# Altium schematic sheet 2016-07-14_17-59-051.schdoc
size 339 x 185 mm; SheetNumber: 1; SheetTotal: 1
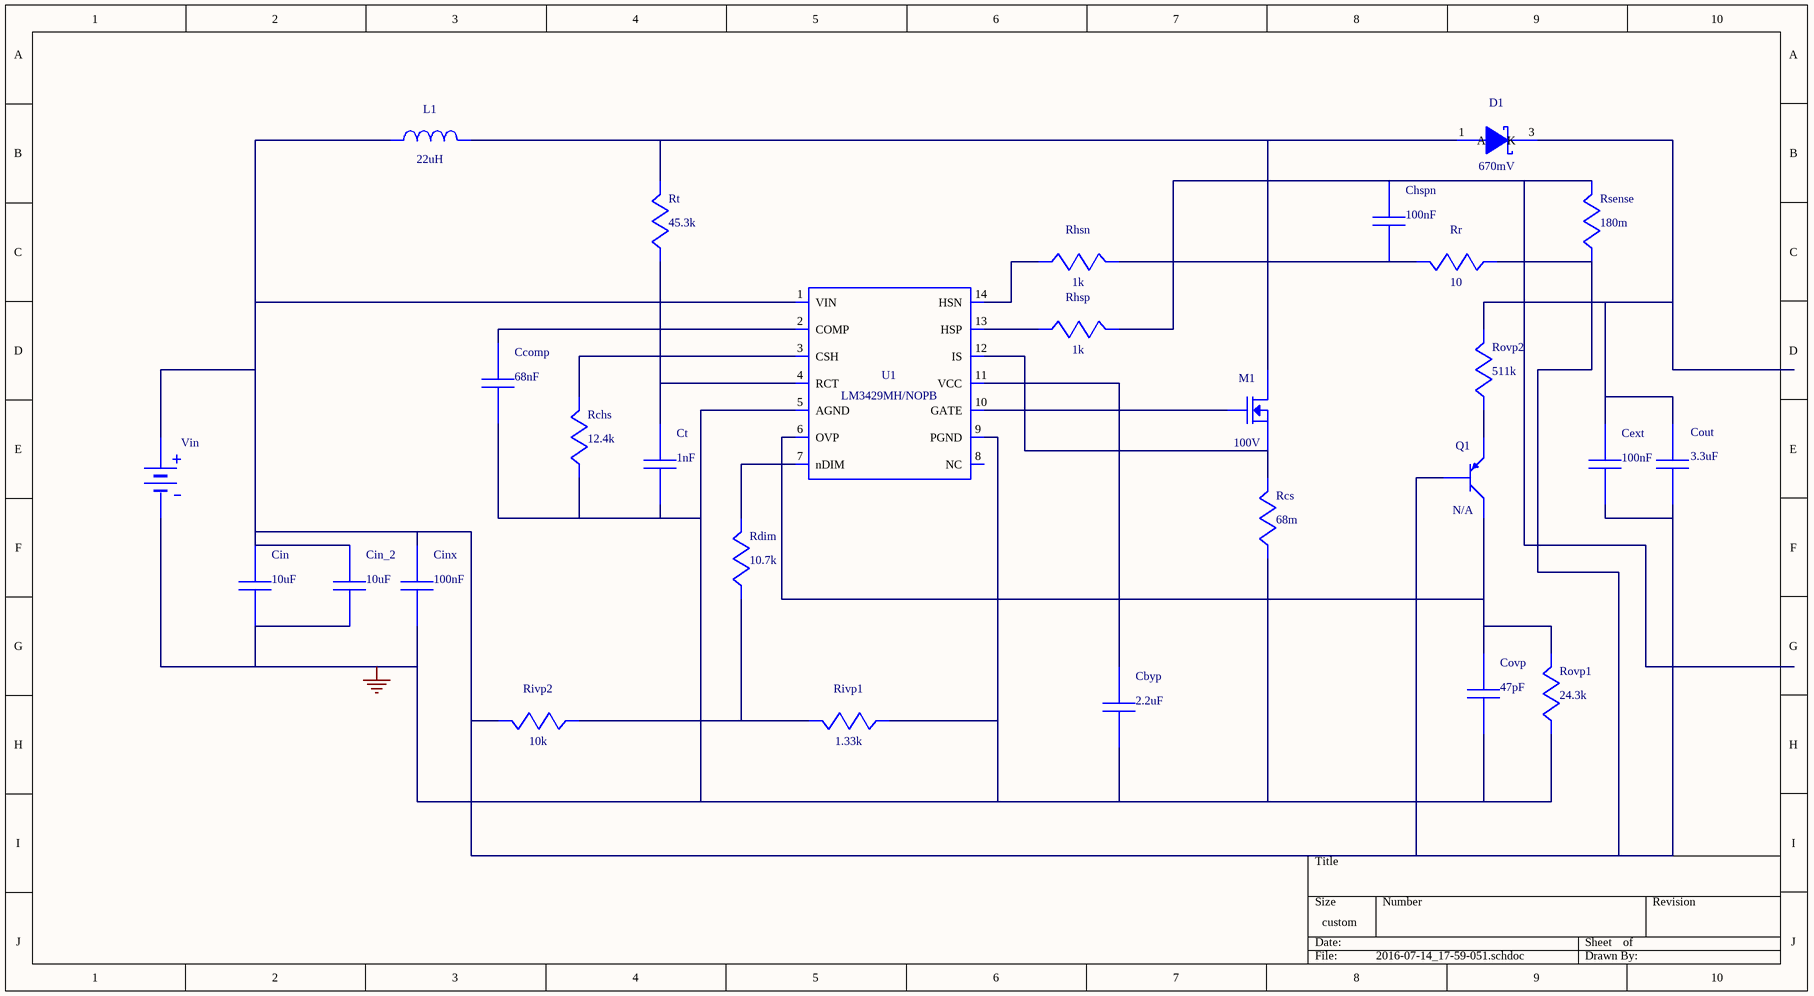
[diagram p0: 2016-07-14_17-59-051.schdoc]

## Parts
Cbyp  value 2.2uF  (hidden comment: EMK212B7225KG-T)
Ccomp  value 68nF  (hidden comment: GRM155R61A683KA01D)
Cext  value 100nF  (hidden comment: 08053C104KAT2A)
Chspn  value 100nF  (hidden comment: GRM21BR71E104KA01L)
Cin  value 10uF  (hidden comment: GRM32ER7YA106KA12L)
Cin_2  value 10uF  (hidden comment: GRM32ER7YA106KA12L)
Cinx  value 100nF  (hidden comment: C0603C104K5RACTU)
Cout  value 3.3uF  (hidden comment: C3225X7S2A335K200AB)
Covp  value 47pF  (hidden comment: C0805C470K5GACTU)
Ct  value 1nF  (hidden comment: CL21C102JBCNFNC)
D1  value 670mV  (hidden comment: FSV8100V)
L1  value 22uH  (hidden comment: SDR1307-220ML)
M1  value 100V  (hidden comment: CSD16323Q3)
Q1  MMBT3906-7-F  (value not drawn)
Rchs  value 12.4k  (hidden comment: CRCW040212K4FKED)
Rcs  value 68m  (hidden comment: CSRN2512FK68L0)
Rdim  value 10.7k  (hidden comment: CRCW040210K7FKED)
Rhsn  value 1k  (hidden comment: CRCW04021K00FKED)
Rhsp  value 1k  (hidden comment: CRCW04021K00FKED)
Rivp1  value 1.33k  (hidden comment: CRCW04021K33FKED)
Rivp2  value 10k  (hidden comment: CRCW040210K0FKED)
Rovp1  value 24.3k  (hidden comment: CRCW040224K3FKED)
Rovp2  value 511k  (hidden comment: CRCW0402511KFKED)
Rr  value 10  (hidden comment: CRCW040210R0FKED)
Rsense  value 180m  (hidden comment: ERJ-3RSFR18V)
Rt  value 45.3k  (hidden comment: CRCW040245K3FKED)
U1  LM3429MH  (value not drawn)
Vin  WB_BATTERY  (value not drawn)

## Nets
0: Cbyp.2 Ccomp.2 Cin.2 Cin_2.2 Cinx.2 Covp.2 Ct.2 Rchs.2 Rcs.2 Rivp1.2 Rovp1.2 U1.5(AGND) U1.9(PGND) U1.15(DAP) Vin.2(-)
NetCbyp_1: Cbyp.1 U1.11(VCC)
NetCcomp_1: Ccomp.1 U1.2(COMP)
NetCext_1: Cext.1 Cout.1 D1.3(K) Rovp2.1
NetCext_2: Cext.2 Cin.1 Cin_2.1 Cinx.1 Cout.2 L1.1 Q1.1(Base) Rivp2.1 Rr.2 Rsense.2 U1.1(VIN) Vin.1(+)
NetChspn_1: Chspn.1 Rhsp.1 Rsense.1
NetChspn_2: Chspn.2 Rhsn.1 Rr.1
NetCovp_1: Covp.1 Q1.3(Collector) Rovp1.1 U1.6(OVP)
NetCt_1: Ct.1 Rt.2 U1.4(RCT)
NetD1_1: D1.1(A) D1.2(A) L1.2 M1.5(Drain) M1.6(Drain) M1.7(Drain) M1.8(Drain) M1.9(Drain) Rt.1
NetM1_1: M1.1(Source) M1.2(Source) M1.3(Source) Rcs.1 U1.12(IS)
NetM1_4: M1.4(Gate) U1.10(GATE)
NetQ1_2: Q1.2(Emitter) Rovp2.2
NetRchs_1: Rchs.1 U1.3(CSH)
NetRdim_1: Rdim.1 U1.7(nDIM)
NetRdim_2: Rdim.2 Rivp1.1 Rivp2.2
NetRhsn_2: Rhsn.2 U1.14(HSN)
NetRhsp_2: Rhsp.2 U1.13(HSP)

Not connected (* = marked no-connect by the designer): U1 8(NC)

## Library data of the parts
Cbyp = EMK212B7225KG-T: Manufacturer Name: Taiyo Yuden
Ccomp = GRM155R61A683KA01D: GRM155R61A683KA0; Manufacturer Name: MuRata
Cext = 08053C104KAT2A: Manufacturer Name: AVX
Chspn = GRM21BR71E104KA01L: GRM21BR71E104KA0; Manufacturer Name: MuRata
Cin Cin_2 = GRM32ER7YA106KA12L: GRM32ER7YA106KA1; Manufacturer Name: MuRata
Cinx = C0603C104K5RACTU: Manufacturer Name: Kemet
Cout = C3225X7S2A335K200AB: C3225X7S2A335K20; Manufacturer Name: TDK
Covp = C0805C470K5GACTU: Manufacturer Name: Kemet
Ct = CL21C102JBCNFNC: Manufacturer Name: Samsung Electro-Mechanics
D1 = FSV8100V: Manufacturer Name: Fairchild Semiconductor
L1 = SDR1307-220ML: Manufacturer Name: Bourns
M1 = CSD16323Q3: CSD19537Q3; Manufacturer Name: Texas Instruments
Q1 = MMBT3906-7-F: Manufacturer Name: Diodes Inc.
Rchs = CRCW040212K4FKED: Manufacturer Name: Vishay-Dale
Rcs = CSRN2512FK68L0: Manufacturer Name: Stackpole Electronics Inc
Rdim = CRCW040210K7FKED: Manufacturer Name: Vishay-Dale
Rhsn Rhsp = CRCW04021K00FKED: Manufacturer Name: Vishay-Dale
Rivp1 = CRCW04021K33FKED: Manufacturer Name: Vishay-Dale
Rivp2 = CRCW040210K0FKED: Manufacturer Name: Vishay-Dale
Rovp1 = CRCW040224K3FKED: Manufacturer Name: Vishay-Dale
Rovp2 = CRCW0402511KFKED: Manufacturer Name: Vishay-Dale
Rr = CRCW040210R0FKED: Manufacturer Name: Vishay-Dale
Rsense = ERJ-3RSFR18V: Manufacturer Name: Panasonic
Rt = CRCW040245K3FKED: Manufacturer Name: Vishay-Dale
U1 = LM3429MH: LM3429MH/NOPB; Manufacturer Name: Texas Instruments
